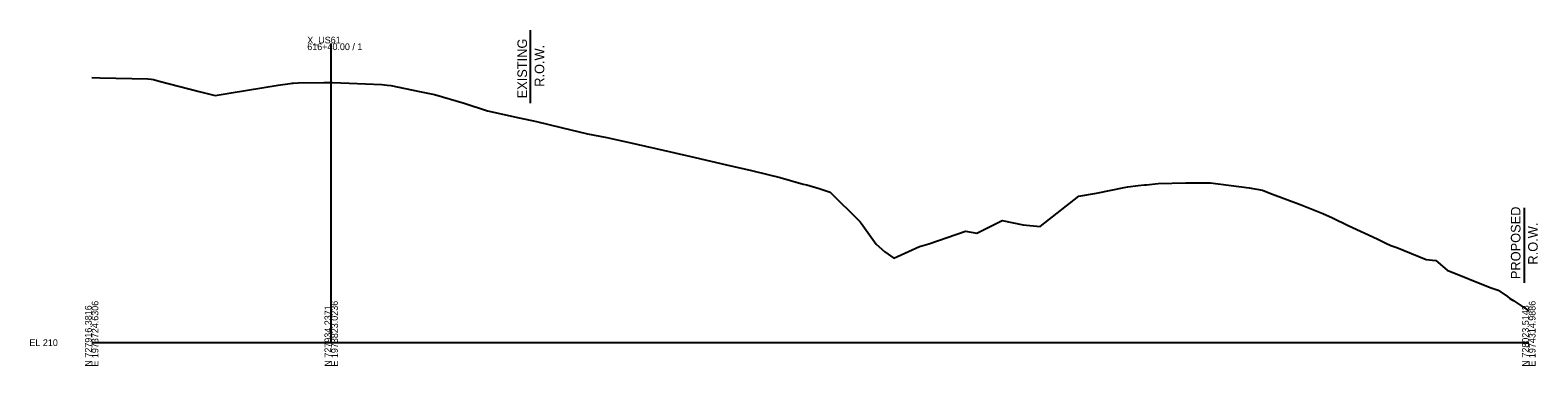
# Model space of a CAD drawing. Extents: x -26 to 1604, y -13 to 9623.
# Drawn here: x 974 to 1604, y 990 to 1131 of the extents above; entities that cross this region are included whole.
import ezdxf

# ---------------------------------------------------------------- set-up
doc = ezdxf.new("R2010")
doc.units = 0
for name, color, linetype in [('Draft_XS_Grid', 7, 'Continuous'), ('DTM_X_GROUND', 7, 'Continuous'), ('XS_CELL', 7, 'Continuous'), ('XS_P_ROW', 7, 'Continuous'), ('XS_X_ROW', 7, 'Continuous')]:
    doc.layers.add(name, color=color, linetype=linetype)

msp = doc.modelspace()

# ---------------------------------------------------------------- linework, layer by layer
at = {"layer": 'DTM_X_GROUND'}
msp.add_lwpolyline([(1000, 1110.72), (1003.46, 1110.64), (1023.44, 1110.16), (1024.89, 1110.02), (1025.8, 1109.93), (1028.13, 1109.19), (1044.85, 1104.88), (1051.52, 1103.2), (1058.28, 1104.36), (1077.89, 1107.6), (1082.91, 1108.26), (1083.72, 1108.37), (1084.14, 1108.39), (1086.26, 1108.48), (1096.93, 1108.64), (1100.53, 1108.69), (1107.44, 1108.39), (1121.09, 1107.79), (1123.43, 1107.53), (1124.88, 1107.36), (1136.84, 1104.96), (1143.19, 1103.71), (1155.47, 1100.09), (1165.32, 1096.77), (1178.41, 1093.94), (1185.74, 1092.4), (1196, 1089.82), (1206.97, 1087.17), (1215.12, 1085.66), (1225.04, 1083.46), (1241.66, 1079.72), (1251.9, 1077.4), (1265.05, 1074.27), (1275.41, 1071.93), (1282.24, 1070.22), (1287.39, 1068.93), (1297.08, 1066.24), (1298.64, 1065.87), (1303.72, 1064.46), (1308.35, 1062.82), (1320.51, 1050.74), (1320.78, 1050.46), (1321.31, 1049.85), (1327.53, 1041.15), (1331.08, 1037.94), (1334.84, 1035.3), (1345.55, 1040.18), (1349.45, 1041.29), (1364.75, 1046.61), (1369.51, 1045.72), (1380.13, 1050.97), (1388.95, 1049.15), (1396.02, 1048.58), (1412.11, 1061.16), (1419.51, 1062.38), (1431.04, 1064.86), (1432.55, 1065.13), (1436.87, 1065.6), (1439.51, 1065.9), (1440.43, 1065.94), (1445.27, 1066.51), (1456.77, 1066.7), (1467.08, 1066.82), (1483.27, 1064.67), (1488.79, 1063.69), (1491.93, 1062.51), (1504.92, 1057.53), (1514.07, 1053.94), (1518.01, 1052.2), (1524.65, 1048.97), (1536.7, 1043.36), (1540.35, 1041.56), (1542.34, 1040.58), (1544.92, 1039.7), (1557.18, 1034.74), (1561.25, 1034.33), (1565.95, 1030.28), (1583.82, 1022.99), (1587.14, 1021.87), (1591.06, 1019.23), (1592.12, 1018.43), (1593.74, 1017.44), (1600, 1013.29)], dxfattribs=at)
at = {"layer": 'XS_CELL'}
for p, q in [((1100, 1000), (1100, 1125)), ((1000, 1000), (1100, 1000)), ((1100, 1000), (1600, 1000))]:
    msp.add_line(p, q, dxfattribs=at)
at = {"layer": 'XS_P_ROW'}
msp.add_line((1598, 1056.27), (1598, 1025), dxfattribs=at)
at = {"layer": 'XS_X_ROW'}
msp.add_line((1183, 1130.55), (1183, 1100), dxfattribs=at)

# ---------------------------------------------------------------- texts
at = {"layer": 'Draft_XS_Grid'}
msp.add_text('-', height=0.0001, dxfattribs=at).set_placement((1000, 1000))
at = {"layer": 'XS_CELL'}
for s, p in [('X_US61', (1090, 1125)), ('616+40.00 / 1', (1090, 1122.2)), ('EL 210', (974, 998.6))]:
    msp.add_text(s, height=2.8, dxfattribs=at).set_placement(p)
for s, p in [('N 727916.3816', (1000, 990)), ('E 1973724.6306', (1002.8, 990)), ('N 727934.2371', (1100, 990)), ('E 1973823.0236', (1102.8, 990)), ('N 728023.5143', (1600, 990)), ('E 1974314.9886', (1602.8, 990))]:
    msp.add_text(s, height=2.8, rotation=90, dxfattribs=at).set_placement(p)
at = {"layer": 'XS_P_ROW'}
for s, p in [('PROPOSED', (1596.52, 1026.54)), ('R.O.W.', (1603.72, 1032.62))]:
    msp.add_text(s, height=4, rotation=90, dxfattribs=at).set_placement(p)
at = {"layer": 'XS_X_ROW'}
for s, p in [('EXISTING', (1181.75, 1102.05)), ('R.O.W.', (1188.95, 1106.89))]:
    msp.add_text(s, height=4, rotation=90, dxfattribs=at).set_placement(p)

doc.saveas('drawing.dxf')
